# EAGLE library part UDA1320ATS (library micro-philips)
Stereo filter D/A CONVERTER
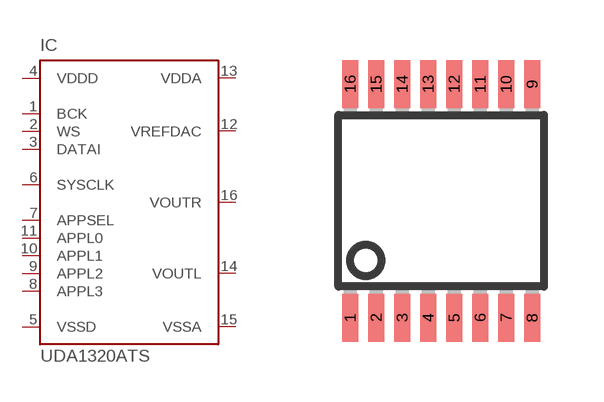
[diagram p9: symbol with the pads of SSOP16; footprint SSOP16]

Designator prefix IC

## UDA1320ATS (OC_FARNELL: unknown; OC_NEWARK: unknown)  [SSOP16]
1  BCK  in
2  WS  in
3  DATAI  in
4  VDDD  pwr
5  VSSD  pwr
6  SYSCLK  in
7  APPSEL  in
8  APPL3  in
9  APPL2  in
10  APPL1  in
11  APPL0  in
12  VREFDAC  in
13  VDDA  pwr
14  VOUTL  out
15  VSSA  pwr
16  VOUTR  out

## Footprint SSOP16 (pad centres in mm)
Small Shrink Outline Package
smd 0.4 x 1.2: 1 -2.275,-2.925; 2 -1.625,-2.925; 3 -0.975,-2.925; 4 -0.325,-2.925; 5 0.325,-2.925; 6 0.975,-2.925; 7 1.625,-2.925; 8 2.275,-2.925; 9 2.275,2.925; 10 1.625,2.925; 11 0.975,2.925; 12 0.325,2.925; 13 -0.325,2.925; 14 -0.975,2.925; 15 -1.625,2.925; 16 -2.275,2.925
